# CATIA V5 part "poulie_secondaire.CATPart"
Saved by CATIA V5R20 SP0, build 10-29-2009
Part number: poulie_secondaire
Bounding box of the stored display mesh (mm): x 605.778 to 685.778, y -88.488 to 351.51, z 884.137 to 1323.792
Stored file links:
  C:\Users\Mike-7\Desktop\MMS_GR3\bfoltzer\CFAO_bfoltzer\poulie_secondaire.CATPart
  D:\ecole\thinkmotion\Eolienne.CATProduct
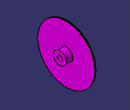
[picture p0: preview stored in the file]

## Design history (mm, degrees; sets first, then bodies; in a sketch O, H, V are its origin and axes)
Set1
  Plane1: linked copy from another document
  Point1 to Point6: linked copy from another document
  Line1: linked copy from another document
  Point7: linked copy from another document
  Point8: linked copy from another document
Body1 (main body)
  Sketch1 on Plane1, origin (0, 706.7524, 3942.1213), H (1, 0, 0), V (0, -0.1986, -0.9801)
    point P1 (635.7782, 2915.8655)
    line L1 (635.7782, 2915.8655) -> (685.7782, 2915.8655)
    line L2 (685.7782, 2915.8655) -> (685.7782, 2945.8655)
    line L3 (685.7782, 2945.8655) -> (635.7782, 2945.8655)
    line L4 (635.7782, 2945.8655) -> (635.7782, 2915.8655)
    point P3 (685.7782, 2945.8655)
    reference projected point E1 (685.7782, 2945.8655) from Point1
    reference projected point E2 (635.7782, 2915.8655) from Point2
    point P5 (625.7782, 2915.8655)
    line L5 (625.7782, 2915.8655) -> (635.7782, 2915.8655)
    line L6 (635.7782, 2915.8655) -> (635.7782, 3115.8655)
    line L7 (635.7782, 3115.8655) -> (625.7782, 3115.8655)
    line L8 (625.7782, 3115.8655) -> (625.7782, 2915.8655)
    point P6 (635.7782, 2915.8655)
    point P7 (635.7782, 3115.8655)
    reference projected point E3 (635.7782, 3115.8655) from Point3
    reference projected point E4 (625.7782, 2915.8655) from Point4
    line L9 (605.7782, 2950.8655) -> (625.7782, 2950.8655)
    line L10 (625.7782, 2950.8655) -> (625.7782, 2930.8655)
    line L11 (625.7782, 2930.8655) -> (605.7782, 2930.8655)
    line L12 (605.7782, 2930.8655) -> (605.7782, 2950.8655)
    point P10 (625.7782, 2950.8655)
    point P12 (605.7782, 2930.8655)
    reference projected point E5 (625.7782, 2950.8655) from Point5
    reference projected point E6 (605.7782, 2930.8655) from Point6
    horizontal: L1 H, L3 H, L5 H, L7 H, L9 H, L11 H
    vertical: L2 V, L4 V, L6 V, L8 V, L10 V, L12 V
    coincidence: P3 E1, P1 E2, P7 E3, P5 E4, P10 E5, P12 E6, P1 P6
  Shaft1: profile Sketch1, axis Line1, angle 360
  Sketch2 on Plane1, origin (0, 706.7524, 3942.1213), H (1, 0, 0), V (0, -0.1986, -0.9801)
    line L1 (629.2782, 3115.8655) -> (632.2782, 3115.8655)
    line L2 (632.2782, 3115.8655) -> (632.2782, 3114.8655)
    line L3 (632.2782, 3114.8655) -> (629.2782, 3114.8655)
    line L4 (629.2782, 3114.8655) -> (629.2782, 3115.8655)
    point P2 (632.2782, 3115.8655)
    point P4 (629.2782, 3114.8655)
    reference projected point E1 (632.2782, 3115.8655) from Point7
    reference projected point E2 (629.2782, 3114.8655) from Point8
    horizontal: L1 H, L3 H
    vertical: L2 V, L4 V
    coincidence: P2 E1, P4 E2
  Groove1: profile Sketch2, axis Line1, angle 360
